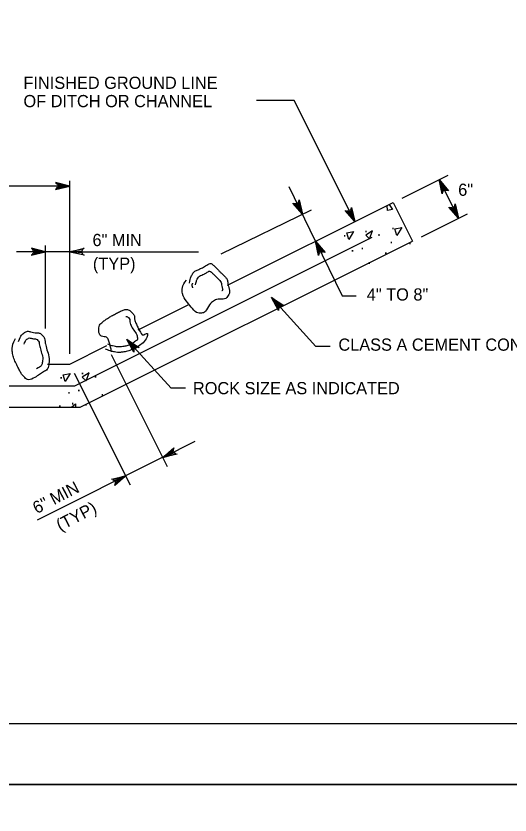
# Model space of a CAD drawing. Extents: x 636183 to 639890, y 299162 to 300538.
# Drawn here: x 638440.6 to 638561.9, y 299936.9 to 300133.4 of the extents above; entities that cross this region are included whole.
import ezdxf

# ---------------------------------------------------------------- set-up
doc = ezdxf.new("R2010")
doc.units = 0
for name, color, linetype in [('1', 7, 'Continuous'), ('Default', 7, 'Continuous'), ('PLT-BNDY', 7, 'Continuous')]:
    doc.layers.add(name, color=color, linetype=linetype)

msp = doc.modelspace()

# ---------------------------------------------------------------- linework, layer by layer
at = {"layer": '1'}
msp.add_lwpolyline([(638969.91, 299959.45), (638969.91, 300523.45), (638183.91, 300523.45), (638183.91, 299959.45), (638969.91, 299959.45), (638969.91, 299985.81), (638769.91, 299985.81), (638769.91, 300050.49), (638969.91, 300050.49), (638969.91, 300079.45), (638769.91, 300079.45), (638769.91, 299959.45), (638848.72, 299959.45), (638848.72, 299985.81), (638848.72, 299959.45), (638925.72, 299959.45), (638925.72, 299985.81), (638925.72, 299973.49), (638969.91, 299973.49)], dxfattribs=at)
at = {"layer": 'Default'}
for p, q in [((638508.92, 300112.61), (638499.7, 300112.61)), ((638535.44, 300088.66), (638546.74, 300094.31)), ((638453.82, 300050.33), (638453.82, 300092.86)), ((638514.2, 300078.04), (638507.69, 300091.41)), ((638492.58, 300067.23), (638533.22, 300087.55)), ((638531.81, 300085.6), (638531.78, 300086.83)), ((638532.27, 300087.08), (638533.04, 300085.88)), ((638533.22, 300087.55), (638537.98, 300078.02)), ((638491, 300074.97), (638513.2, 300085.78)), ((638533.04, 300085.88), (638531.81, 300085.6)), ((638540.21, 300079.14), (638551.5, 300084.78)), ((638521.86, 300080.08), (638523.52, 300080.41)), ((638522.32, 300078.43), (638521.86, 300080.08)), ((638523.52, 300080.41), (638522.32, 300078.43)), ((638447.87, 300056.57), (638447.87, 300076.96)), ((638453.67, 300075.45), (638440.7, 300075.45)), ((638520.72, 300064.63), (638524.18, 300064.63)), ((638470.57, 300056.22), (638482.93, 300062.4)), ((638464.02, 300050.17), (638477.77, 300022.67)), ((638454.93, 300045.63), (638468.68, 300018.13)), ((638454.2, 300037.2), (638455.22, 300038.09)), ((638455.22, 300038.09), (638455.2, 300037.2))]:
    msp.add_line(p, q, dxfattribs=at)
for points in [[(638523.85, 300082.86), (638508.92, 300112.61)], [(638450.59, 300090.98), (638450.32, 300090.76), (638453.82, 300091.62), (638450.59, 300090.98), (638450.79, 300091.35), (638453.82, 300091.62), (638450.79, 300091.88), (638450.61, 300092.25), (638453.82, 300091.62), (638450.32, 300092.5), (638450.61, 300092.25)], [(638544.52, 300093.2), (638549.28, 300083.67)], [(638545.38, 300090.02), (638545.3, 300089.68), (638544.52, 300093.2), (638545.38, 300090.02), (638545.63, 300090.36), (638544.52, 300093.2), (638546.09, 300090.6), (638546.51, 300090.6), (638544.52, 300093.2), (638546.86, 300090.46), (638546.51, 300090.6)], [(638453.82, 300091.62), (638411.04, 300091.62)], [(638510.09, 300087.87), (638510.17, 300088.21), (638510.96, 300084.69), (638510.09, 300087.87), (638509.84, 300087.52), (638510.96, 300084.69), (638509.38, 300087.28), (638508.96, 300087.28), (638510.96, 300084.69), (638508.61, 300087.42), (638508.96, 300087.28)], [(638548.38, 300086.87), (638548.46, 300087.21), (638549.26, 300083.69), (638548.38, 300086.87), (638548.14, 300086.53), (638549.26, 300083.69), (638547.67, 300086.28), (638547.25, 300086.28), (638549.26, 300083.69), (638546.9, 300086.42), (638547.25, 300086.28)], [(638522.95, 300086.03), (638523.03, 300086.38), (638523.85, 300082.86), (638522.95, 300086.03), (638522.71, 300085.69), (638523.85, 300082.86), (638522.25, 300085.45), (638521.83, 300085.44), (638523.85, 300082.86), (638521.48, 300085.58), (638521.83, 300085.44)], [(638308.28, 300079.91), (638383.04, 300042.52), (638455.08, 300042.52), (638528.09, 300079.03)], [(638300.14, 300078.02), (638381.79, 300037.2), (638456.33, 300037.2), (638537.98, 300078.02)], [(638515.02, 300074.85), (638514.94, 300074.51), (638514.2, 300078.04), (638515.02, 300074.85), (638515.27, 300075.19), (638514.2, 300078.04), (638515.74, 300075.42), (638516.16, 300075.42), (638514.2, 300078.04), (638516.51, 300075.27), (638516.16, 300075.42)], [(638514.2, 300078.04), (638520.72, 300064.63)], [(638444.64, 300074.81), (638444.37, 300074.58), (638447.87, 300075.45), (638444.64, 300074.81), (638444.84, 300075.18), (638447.87, 300075.45), (638444.84, 300075.7), (638444.66, 300076.08), (638447.87, 300075.45), (638444.38, 300076.33), (638444.66, 300076.08)], [(638457.05, 300074.81), (638457.32, 300074.58), (638453.82, 300075.45), (638457.05, 300074.81), (638456.86, 300075.18), (638453.82, 300075.45), (638456.85, 300075.7), (638457.03, 300076.08), (638453.82, 300075.45), (638457.32, 300076.33), (638457.03, 300076.08)], [(638453.82, 300075.45), (638485.44, 300075.45)], [(638505.07, 300061.38), (638505.09, 300061.03), (638503.35, 300064.19), (638505.07, 300061.38), (638505.21, 300061.77), (638503.35, 300064.19), (638505.59, 300062.13), (638505.99, 300062.25), (638503.35, 300064.19), (638506.37, 300062.22), (638505.99, 300062.25)], [(638517.73, 300052.19), (638514.25, 300052.19), (638503.35, 300064.19)], [(638482.21, 300041.91), (638478.73, 300041.91), (638467.83, 300053.91)], [(638469.56, 300051.1), (638469.58, 300050.75), (638467.83, 300053.91), (638469.56, 300051.1), (638469.7, 300051.5), (638467.83, 300053.91), (638470.08, 300051.86), (638470.48, 300051.98), (638467.83, 300053.91), (638470.86, 300051.95), (638470.48, 300051.98)], [(638448.37, 300047.85), (638453.82, 300047.85), (638462.91, 300052.39)], [(638476.66, 300024.9), (638484.63, 300028.88)], [(638479.84, 300025.76), (638480.18, 300025.68), (638476.66, 300024.9), (638479.84, 300025.76), (638479.49, 300026.01), (638476.66, 300024.9), (638479.26, 300026.48), (638479.25, 300026.89), (638476.66, 300024.9), (638479.39, 300027.25), (638479.25, 300026.89)], [(638477.01, 300025.08), (638445.84, 300009.49)], [(638464.39, 300019.48), (638464.05, 300019.56), (638467.57, 300020.35), (638464.39, 300019.48), (638464.73, 300019.24), (638467.57, 300020.35), (638464.97, 300018.77), (638464.98, 300018.35), (638467.57, 300020.35), (638464.84, 300018), (638464.98, 300018.35)]]:
    msp.add_lwpolyline(points, dxfattribs=at)
for points in [[(638528.2, 300080.57), (638526.5, 300079.51), (638527.46, 300078.64)], [(638533.67, 300081.13), (638535.33, 300081.46), (638534.14, 300079.48)], [(638452.23, 300045.17), (638453.89, 300045.5), (638452.69, 300043.53)], [(638458.57, 300045.67), (638456.87, 300044.6), (638457.83, 300043.74)]]:
    msp.add_lwpolyline(points, close=True, dxfattribs=at)
for points, degree in [([(638483.21, 300067.74), (638483.36, 300068.5), (638483.5, 300069.24), (638483.94, 300069.95), (638484.45, 300070.75), (638485.34, 300071.01), (638486.15, 300071.42), (638487.09, 300071.89), (638488.38, 300072.87), (638489.1, 300072.16), (638489.59, 300071.67), (638490.08, 300071.18), (638490.57, 300070.68), (638491.06, 300070.19), (638491.55, 300069.71), (638492.04, 300069.21), (638492.59, 300068.67), (638492.61, 300067.75), (638492.78, 300067), (638492.94, 300066.3), (638493.18, 300065.47), (638492.78, 300064.8), (638492.06, 300063.59), (638490.05, 300063.96), (638489.1, 300063.32), (638488.09, 300062.66), (638487.16, 300060.49), (638486.15, 300060.38), (638485.02, 300060.26), (638483.59, 300061.88), (638482.47, 300063.32), (638481.25, 300064.9), (638481.32, 300067.18), (638482.47, 300068.48)], 3), ([(638484.73, 300067.35), (638484.84, 300067.9), (638484.94, 300068.43), (638485.26, 300068.95), (638485.61, 300069.51), (638486.23, 300069.69), (638486.8, 300069.97), (638487.37, 300070.26), (638488.18, 300070.87), (638488.62, 300070.43), (638488.9, 300070.15), (638489.18, 300069.86), (638489.47, 300069.58), (638489.87, 300069.18), (638490.27, 300068.78), (638490.68, 300068.37), (638491.08, 300067.96), (638491.09, 300067.3), (638491.22, 300066.75), (638491.28, 300066.46), (638491.43, 300066.12), (638491.22, 300065.85), (638491.21, 300065.85), (638491.2, 300065.85), (638491.19, 300065.85)], 3), ([(638484.04, 300066.58), (638483.91, 300066.96), (638483.81, 300067.39), (638484.04, 300067.73)], 2), ([(638464.07, 300050.81), (638463.92, 300051.81), (638463.63, 300052.79), (638463.33, 300053.75), (638463.07, 300054.6), (638461.38, 300054.55), (638461.12, 300055.23), (638460.83, 300056), (638461.05, 300057.52), (638461.86, 300058.17), (638462.57, 300058.74), (638463.28, 300059.19), (638464.07, 300059.64), (638465.04, 300060.21), (638466.03, 300060.75), (638467.01, 300061.11), (638467.71, 300061.37), (638468.63, 300061.08), (638469.22, 300060.38), (638469.81, 300059.68), (638469.66, 300058.89), (638469.96, 300058.17), (638470.38, 300057.16), (638470.89, 300056.15), (638471.43, 300055.23), (638471.67, 300054.82), (638472.9, 300055.49), (638472.9, 300055.23), (638472.9, 300054.56), (638471.82, 300052.9), (638470.69, 300052.28), (638469.49, 300051.61), (638468.32, 300051.02), (638467.01, 300050.81), (638466.28, 300050.7), (638465.53, 300050.67), (638464.8, 300050.81), (638464.04, 300050.96), (638463.31, 300051.17), (638462.6, 300051.54)], 3), ([(638467.6, 300059.52), (638467.79, 300059.55), (638467.99, 300059.51), (638468.17, 300059.33), (638468.7, 300058.8), (638468.51, 300058.19), (638468.72, 300057.66), (638469.2, 300056.49), (638470.27, 300055.33), (638470.46, 300054.19), (638470.51, 300053.89), (638470.16, 300053.62), (638469.85, 300053.38), (638468.85, 300052.58), (638467.86, 300052.32), (638466.76, 300052.14), (638466.18, 300052.05), (638465.59, 300052.03), (638465.02, 300052.14), (638464.39, 300052.27), (638463.78, 300052.44), (638463.19, 300052.75)], 3), ([(638441.25, 300053.39), (638441.57, 300054.22), (638441.91, 300055.06), (638442.72, 300055.59), (638443.4, 300056.04), (638444.21, 300055.73), (638444.93, 300055.59), (638445.69, 300055.46), (638446.51, 300055.54), (638447.14, 300054.86), (638447.76, 300054.18), (638447.69, 300053.41), (638447.87, 300052.65), (638448.29, 300050.96), (638448.94, 300049.18), (638448.61, 300047.5), (638448.41, 300046.49), (638447.33, 300045.91), (638446.4, 300045.29), (638445.29, 300044.54), (638443.63, 300043.71), (638442.72, 300044.55), (638442.08, 300045.14), (638441.67, 300045.94), (638441.25, 300046.76), (638440.62, 300047.98), (638440.04, 300049.19), (638439.77, 300050.44), (638439.52, 300051.62), (638439.86, 300052.95), (638440.51, 300054.12)], 3), ([(638442.6, 300052.73), (638442.8, 300053.25), (638443.01, 300053.77), (638443.52, 300054.1), (638443.88, 300054.34), (638444.3, 300054.17), (638444.69, 300054.1), (638445.12, 300054.02), (638445.6, 300054.07), (638445.96, 300053.68), (638446.34, 300053.26), (638446.3, 300052.78), (638446.41, 300052.3), (638446.76, 300050.9), (638447.3, 300049.42), (638447.03, 300048.02), (638446.9, 300047.4), (638446.23, 300047.05), (638445.66, 300046.66)], 3)]:
    msp.add_open_spline(points, degree=degree, dxfattribs=at)
at = {"layer": 'PLT-BNDY'}
for points in [[(638143.91, 300538.45), (638984.91, 300538.45), (638984.91, 299944.45), (638143.91, 299944.45)], [(638143.91, 299944.45), (638984.91, 299944.45), (638984.91, 299350.45), (638143.91, 299350.45)]]:
    msp.add_lwpolyline(points, close=True, dxfattribs=at)

# ---------------------------------------------------------------- texts
at = {"layer": 'Default'}
for s, height, p in [('FINISHED GROUND LINE', 2.998, (638442.44, 300115.51)), ('OF DITCH OR CHANNEL', 2.998, (638442.44, 300111.01)), ('6"', 2.998, (638549.21, 300089.21)), ('.', 2.83, (638526.04, 300080.23)), ('.', 2.83, (638532.65, 300080.97)), ('6" MIN', 2.998, (638459.39, 300076.85)), ('.', 2.83, (638520.8, 300079.14)), ('.', 2.83, (638520.8, 300079.14)), ('.', 2.83, (638529.24, 300079.36)), ('.', 2.83, (638532.26, 300077.52)), ('.', 2.83, (638536.84, 300077.25)), ('.', 2.83, (638522.73, 300075.46)), ('.', 2.83, (638525.13, 300076.04)), ('.', 2.83, (638530.91, 300074.9)), (' (TYP)', 2.998, (638458.38, 300071.04)), ('.', 2.83, (638526.88, 300072.47)), ('4" TO 8"', 2.998, (638526.76, 300063.46)), ('CLASS A CEMENT CONCRETE', 2.998, (638519.79, 300051.12)), ('.', 2.83, (638456.41, 300045.32)), ('.', 2.83, (638451.17, 300044.23)), ('.', 2.83, (638451.17, 300044.23)), ('.', 2.83, (638459.62, 300044.46)), ('ROCK SIZE AS INDICATED', 2.998, (638484.06, 300040.42)), ('.', 2.83, (638455.5, 300041.13)), ('.', 2.83, (638453.1, 300040.55)), ('.', 2.83, (638461.28, 300040)), ('.', 2.83, (638450.85, 300037.24)), ('.', 2.83, (638454.02, 300037.88)), ('.', 2.83, (638457.25, 300037.57))]:
    msp.add_text(s, height=height, dxfattribs=at).set_placement(p)
for s, p in [('6" MIN', (638445.69, 300010.93)), ('(TYP)', (638451.45, 300006.68))]:
    msp.add_text(s, height=2.998, rotation=27.4076, dxfattribs=at).set_placement(p)

doc.saveas('drawing.dxf')
